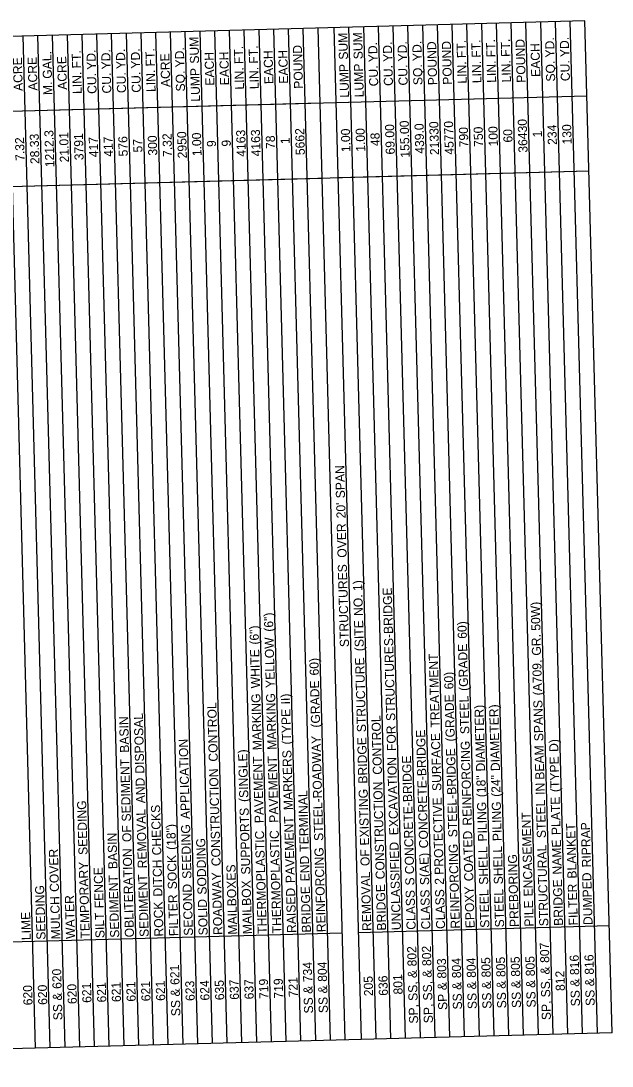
# Model space of a CAD drawing. Extents: x 1930093 to 1931323, y 596452 to 607874.
# Drawn here: x 1930614 to 1931004, y 606441 to 607132 of the extents above; entities that cross this region are included whole.
import ezdxf

# ---------------------------------------------------------------- set-up
doc = ezdxf.new("R2010")
doc.units = 0
doc.layers.add('Default', color=7, linetype='Continuous')

msp = doc.modelspace()

# ---------------------------------------------------------------- linework, layer by layer
at = {"layer": 'Default'}
for p, q in [((1930986.43, 607132.14), (1930166.75, 607110.14)), ((1930984.9, 606462.52), (1930966.94, 607131.62)), ((1930994.65, 606462.78), (1930976.69, 607131.88)), ((1931004.39, 606463.04), (1930986.43, 607132.14)), ((1930720.77, 606455.43), (1930702.81, 607124.53)), ((1930730.52, 606455.69), (1930712.56, 607124.79)), ((1930740.26, 606455.95), (1930722.3, 607125.05)), ((1930750.01, 606456.22), (1930732.05, 607125.31)), ((1930759.76, 606456.48), (1930741.79, 607125.57)), ((1930769.5, 606456.74), (1930751.54, 607125.83)), ((1930779.25, 606457), (1930761.29, 607126.1)), ((1930789, 606457.26), (1930771.03, 607126.36)), ((1930798.74, 606457.52), (1930780.78, 607126.62)), ((1930808.49, 606457.79), (1930790.53, 607126.88)), ((1930818.24, 606458.05), (1930800.27, 607127.14)), ((1930827.98, 606458.31), (1930810.02, 607127.4)), ((1930811.35, 607077.7), (1930810.02, 607127.4)), ((1930838.7, 606458.6), (1930820.74, 607127.69)), ((1930848.45, 606458.86), (1930830.49, 607127.95)), ((1930858.2, 606459.12), (1930840.23, 607128.22)), ((1930867.94, 606459.38), (1930849.98, 607128.48)), ((1930877.69, 606459.64), (1930859.73, 607128.74)), ((1930887.44, 606459.9), (1930869.47, 607129)), ((1930897.18, 606460.17), (1930879.22, 607129.26)), ((1930906.93, 606460.43), (1930888.97, 607129.52)), ((1930916.67, 606460.69), (1930898.71, 607129.79)), ((1930926.42, 606460.95), (1930908.46, 607130.05)), ((1930936.17, 606461.21), (1930918.21, 607130.31)), ((1930945.91, 606461.47), (1930927.95, 607130.57)), ((1930955.66, 606461.74), (1930937.7, 607130.83)), ((1930965.41, 606462), (1930947.45, 607131.09)), ((1930975.15, 606462.26), (1930957.19, 607131.36)), ((1930623.31, 606452.81), (1930605.34, 607121.91)), ((1930633.05, 606453.08), (1930615.09, 607122.17)), ((1930642.8, 606453.34), (1930624.84, 607122.43)), ((1930652.54, 606453.6), (1930634.58, 607122.7)), ((1930662.29, 606453.86), (1930644.33, 607122.96)), ((1930672.04, 606454.12), (1930654.08, 607123.22)), ((1930681.78, 606454.38), (1930663.82, 607123.48)), ((1930691.53, 606454.65), (1930673.57, 607123.74)), ((1930701.28, 606454.91), (1930683.32, 607124)), ((1930711.02, 606455.17), (1930693.06, 607124.27)), ((1930987.77, 607082.43), (1930168.09, 607060.43)), ((1930811.35, 607077.7), (1930168.09, 607060.43)), ((1930987.77, 607082.43), (1930822.08, 607077.99)), ((1930989.1, 607032.73), (1930169.42, 607010.72)), ((1930812.69, 607027.99), (1930198.66, 607011.51)), ((1930989.1, 607032.73), (1930823.41, 607028.28)), ((1931002.5, 606533.71), (1930836.81, 606529.26)), ((1931002.5, 606533.71), (1930836.81, 606529.26)), ((1930826.08, 606528.97), (1930182.82, 606511.7)), ((1930826.08, 606528.97), (1930212.06, 606512.49)), ((1931004.39, 606463.04), (1930184.71, 606441.04)), ((1931004.39, 606463.04), (1930184.71, 606441.04))]:
    msp.add_line(p, q, dxfattribs=at)

# ---------------------------------------------------------------- texts
for s, p in [(' SUM', (1930731.48, 607101.72)), (' SUM', (1930829.92, 607104.37)), (' SUM', (1930839.67, 607104.63)), (' YD.', (1930859.22, 607102.92)), (' YD.', (1930868.97, 607103.18)), (' YD.', (1930878.71, 607103.45)), ('POUND', (1930888.83, 607089.73)), ('POUND', (1930898.58, 607089.99)), (' FT.', (1930907.92, 607105.4)), (' FT.', (1930917.67, 607105.66)), (' FT.', (1930927.41, 607105.92)), (' FT.', (1930937.16, 607106.18)), ('POUND', (1930947.31, 607091.3)), (' YD.', (1930966.43, 607105.8)), (' YD.', (1930976.18, 607106.06)), (' GAL.', (1930634.21, 607091.75)), (' FT.', (1930653.54, 607098.57)), (' YD.', (1930663.32, 607097.66)), (' YD.', (1930673.06, 607097.92)), (' YD.', (1930682.81, 607098.19)), (' YD.', (1930692.56, 607098.45)), (' FT.', (1930702.27, 607099.88)), (' YD.', (1930721.79, 607099.23)), ('EACH', (1930741.57, 607089.38)), ('EACH', (1930751.31, 607089.64)), (' FT.', (1930760.75, 607101.45)), (' FT.', (1930770.5, 607101.71)), ('EACH', (1930780.55, 607090.43)), ('EACH', (1930790.3, 607090.69)), ('POUND', (1930800.14, 607087.35)), (' YD.', (1930849.47, 607102.66)), ('EACH', (1930956.96, 607095.16)), ('ACRE', (1930614.86, 607085.87)), ('ACRE', (1930624.61, 607086.13)), ('ACRE', (1930644.1, 607086.65)), ('ACRE', (1930712.33, 607088.48)), ('LIN.', (1930908.31, 607090.76)), ('LIN.', (1930918.06, 607091.03)), ('LIN.', (1930927.81, 607091.29)), ('LIN.', (1930937.55, 607091.55)), ('SQ.', (1930966.8, 607092.1)), ('CU.', (1930976.55, 607092.36)), ('LIN.', (1930653.93, 607083.93)), ('CU.', (1930663.68, 607083.96)), ('CU.', (1930673.43, 607084.22)), ('CU.', (1930683.18, 607084.48)), ('CU.', (1930692.92, 607084.75)), ('LIN.', (1930702.66, 607085.24)), ('SQ.', (1930722.16, 607085.53)), ('LUMP', (1930732.1, 607078.81)), ('LIN.', (1930761.14, 607086.81)), ('LIN.', (1930770.89, 607087.07)), ('LUMP', (1930830.54, 607081.45)), ('LUMP', (1930840.28, 607081.71)), ('CU.', (1930849.84, 607088.96)), ('CU.', (1930859.59, 607089.22)), ('CU.', (1930869.33, 607089.48)), ('SQ.', (1930879.08, 607089.74)), ('M.', (1930634.44, 607083.18)), ('69.00', (1930860.81, 607043.87)), ('155.00', (1930870.61, 607041.8)), ('439.0', (1930880.3, 607044.39)), ('21330', (1930890.08, 607043.49)), ('45770', (1930899.82, 607043.75)), ('36430', (1930948.55, 607045.06)), ('234', (1930967.92, 607050.24)), ('130', (1930977.67, 607050.5)), ('28.33', (1930625.92, 607037.55)), ('1212.3', (1930635.72, 607035.48)), ('21.01', (1930645.39, 607038.65)), ('3791', (1930655.11, 607040.08)), ('576', (1930684.3, 607042.61)), ('300', (1930703.79, 607043.15)), ('7.32', (1930713.57, 607042.27)), ('2950', (1930723.35, 607041.34)), ('1.00', (1930733.06, 607042.77)), ('4163', (1930762.33, 607042.38)), ('4163', (1930772.08, 607042.64)), ('78', (1930781.7, 607047.55)), ('5662', (1930801.32, 607043.46)), ('1.00', (1930831.5, 607045.41)), ('1.00', (1930841.25, 607045.67)), ('48', (1930850.9, 607049.41)), ('790', (1930909.44, 607048.67)), ('750', (1930919.19, 607048.93)), ('100', (1930928.94, 607049.19)), ('60', (1930938.62, 607051.78)), ('1', (1930958.04, 607055.2)), ('7.32', (1930616.11, 607039.65)), ('417', (1930664.81, 607042.09)), ('417', (1930674.55, 607042.35)), ('57', (1930693.98, 607045.2)), ('9', (1930742.65, 607048.84)), ('9', (1930752.4, 607049.1)), ('1', (1930791.37, 607050.73)), (' SPAN', (1930827.95, 606814.35)), (" 20'", (1930828.31, 606801.08)), (' OVER', (1930829.01, 606775.04)), ('STRUCTURES', (1930830.53, 606718.18)), (' 1)', (1930839.35, 606753.02)), (' NO.', (1930839.8, 606736.52)), (' STRUCTURES-BRIDGE', (1930861.17, 606667.12)), (' 50W)', (1930957.1, 606726.76)), (' (6")', (1930780.58, 606726.12)), (' (6")', (1930771.05, 606717.58)), (' (SITE', (1930840.42, 606713.23)), (' 60)', (1930908.47, 606721.44)), (' YELLOW', (1930781.58, 606688.96)), (' GR.', (1930957.54, 606710.27)), (' (GRADE', (1930909.4, 606686.97)), (' WHITE', (1930771.83, 606688.7)), (' 60)', (1930810.62, 606697.17)), (' STRUCTURE', (1930841.86, 606659.66)), (' TREATMENT', (1930890.54, 606662.72)), (' (A709,', (1930958.25, 606684.01)), (' 60)', (1930899.62, 606688)), (' (GRADE', (1930811.54, 606662.7)), (' MARKING', (1930772.93, 606647.78)), (' MARKING', (1930782.67, 606648.05)), (' II)', (1930791.62, 606678.05)), (' (GRADE', (1930900.54, 606653.52)), (' STEEL', (1930910.17, 606658.39)), (' SPANS', (1930959.06, 606653.7)), (' CONTROL', (1930743.87, 606640.22)), (' (TYPE', (1930792.33, 606651.49)), (' DIAMETER)', (1930920.58, 606633.68)), (' DIAMETER)', (1930930.33, 606633.94)), (' BASIN', (1930685.19, 606646.08)), (' DISPOSAL', (1930695.32, 606632.24)), (' CONTROL', (1930852.37, 606631.56)), (' FOR', (1930861.7, 606647.21)), (' CONCRETE-BRIDGE', (1930882.93, 606582.93)), (' APPLICATION', (1930725.38, 606602.23)), (' STEEL-ROADWAY', (1930813.55, 606587.79)), (' BRIDGE', (1930842.77, 606625.65)), (' SURFACE', (1930891.67, 606620.79)), (' REINFORCING', (1930911.79, 606597.92)), (' D)', (1930969, 606646.63)), (' (SINGLE)', (1930764.09, 606613.54)), (' MARKERS', (1930793.5, 606608.15)), (' STEEL-BRIDGE', (1930902.24, 606590.17)), (' BEAM', (1930959.74, 606628.25)), (' SEDIMENT', (1930686.41, 606600.61)), (' PAVEMENT', (1930774.22, 606599.52)), (' PAVEMENT', (1930783.97, 606599.78)), (' EXCAVATION', (1930863.19, 606591.54)), (' CONCRETE-BRIDGE', (1930873.64, 606565.77)), (' (TYPE', (1930969.72, 606620.07)), (' CONSTRUCTION', (1930745.73, 606571.06)), (' AND', (1930695.84, 606612.66)), (' CONSTRUCTION', (1930854.22, 606562.41)), (' (18"', (1930921.04, 606616.67)), (' (24"', (1930930.79, 606616.93)), (' IN', (1930960.01, 606618.23)), (' TERMINAL', (1930803.99, 606580.65)), (' EXISTING', (1930843.87, 606584.73)), (' SEEDING', (1930657.75, 606578.49)), (' CHECKS', (1930706.52, 606578.23)), (' PROTECTIVE', (1930893.16, 606565.36)), (' PILING', (1930921.83, 606587.39)), (' PILING', (1930931.57, 606587.65)), (' STEEL', (1930960.78, 606589.65)), (' PLATE', (1930970.48, 606591.64)), (' REMOVAL', (1930697, 606569.65)), (' SUPPORTS', (1930765.38, 606565.55)), (' ENCASEMENT', (1930952.06, 606551.06)), (' OF', (1930686.78, 606587.03)), (' (18")', (1930716.18, 606581.85)), (' SEEDING', (1930726.44, 606562.71)), (' PAVEMENT', (1930794.79, 606559.89)), (' BLANKET', (1930981.01, 606562.88)), (' RIPRAP', (1930990.56, 606570.26)), (' BASIN', (1930677.5, 606569.13)), ('THERMOPLASTIC', (1930776.13, 606528.6)), ('THERMOPLASTIC', (1930785.87, 606528.87)), (' COATED', (1930912.78, 606561.11)), (' SODDING', (1930736.48, 606552.26)), ('UNCLASSIFIED', (1930864.82, 606530.99)), ('REINFORCING', (1930903.81, 606532.03)), (' SHELL', (1930922.59, 606558.81)), (' SHELL', (1930932.34, 606559.07)), ('STRUCTURAL', (1930962.28, 606533.6)), (' NAME', (1930971.18, 606565.55)), (' COVER', (1930638.89, 606554.06)), ('OBLITERATION', (1930688.41, 606526.25)), (' SOCK', (1930716.88, 606555.79)), (' END', (1930804.52, 606561.07)), ('REINFORCING', (1930815.11, 606529.65)), (' OF', (1930844.23, 606571.15)), (' S(AE)', (1930883.59, 606558.55)), ('PREBORING', (1930942.79, 606533.08)), ('TEMPORARY', (1930659.17, 606525.46)), (' FENCE', (1930668.44, 606543.25)), (' DITCH', (1930707.25, 606550.97)), ('MAILBOXES', (1930756.63, 606528.08)), ('SEDIMENT', (1930678.66, 606525.99)), ('SEDIMENT', (1930698.15, 606526.51)), ('ROADWAY', (1930746.89, 606527.82)), ('REMOVAL', (1930845.33, 606530.46)), (' S', (1930873.84, 606558.29)), (' 2', (1930893.33, 606558.82)), ('DUMPED', (1930991.52, 606534.39)), ('SEEDING', (1930629.93, 606524.68)), ('SECOND', (1930727.39, 606527.3)), ('MAILBOX', (1930766.38, 606528.34)), ('RAISED', (1930795.62, 606529.13)), ('BRIDGE', (1930805.37, 606529.39)), ('BRIDGE', (1930855.07, 606530.72)), ('EPOXY', (1930913.55, 606532.29)), ('STEEL', (1930933.05, 606532.82)), ('BRIDGE', (1930972.03, 606533.86)), ('FILTER', (1930981.78, 606534.13)), ('MULCH', (1930639.68, 606524.94)), ('WATER', (1930649.42, 606525.2)), ('FILTER', (1930717.65, 606527.03)), ('SOLID', (1930737.14, 606527.56)), ('CLASS', (1930874.57, 606531.25)), ('CLASS', (1930884.31, 606531.51)), ('CLASS', (1930894.06, 606531.77)), ('STEEL', (1930923.3, 606532.56)), ('ROCK', (1930707.9, 606526.77)), ('PILE', (1930952.54, 606533.34)), ('LIME', (1930620.18, 606524.42)), ('SILT', (1930668.92, 606525.73)), (' 802', (1930875.28, 606504.8)), (' 802', (1930885.02, 606505.06)), (' 807', (1930963, 606507.12)), (' 734', (1930806.31, 606494.37)), (' 804', (1930816.05, 606494.63)), (' 803', (1930895, 606496.77)), (' 804', (1930904.75, 606497.01)), (' 804', (1930914.49, 606497.27)), (' 805', (1930924.24, 606497.5)), (' 805', (1930933.99, 606497.76)), (' 805', (1930943.73, 606498.02)), (' 805', (1930953.48, 606498.28)), (' 816', (1930982.72, 606499.09)), (' 816', (1930992.46, 606499.35)), (' 620', (1930640.62, 606489.92)), (' 621', (1930718.57, 606492.58)), (' &', (1930875.48, 606497.08)), (' &', (1930885.23, 606497.34)), (' &', (1930963.2, 606499.4)), ('812', (1930973.19, 606490.79)), ('621', (1930660.31, 606482.94)), ('621', (1930670.06, 606483.2)), ('621', (1930679.8, 606483.47)), ('621', (1930689.55, 606483.73)), ('621', (1930699.3, 606483.99)), ('621', (1930709.04, 606484.25)), ('623', (1930728.55, 606484.19)), ('624', (1930738.3, 606484.47)), ('635', (1930748.04, 606484.69)), ('637', (1930757.79, 606484.98)), ('637', (1930767.54, 606485.24)), ('719', (1930777.28, 606485.5)), ('719', (1930787.03, 606485.76)), ('721', (1930796.76, 606486.6)), ('205', (1930846.48, 606487.34)), ('636', (1930856.23, 606487.62)), ('801', (1930865.96, 606488.46)), (' SS,', (1930875.89, 606481.99)), (' SS,', (1930885.63, 606482.25)), (' &', (1930895.21, 606489.05)), (' &', (1930904.95, 606489.29)), (' &', (1930914.7, 606489.55)), (' &', (1930924.45, 606489.77)), (' &', (1930934.19, 606490.04)), (' &', (1930943.94, 606490.3)), (' &', (1930953.69, 606490.56)), (' SS,', (1930963.61, 606484.31)), (' &', (1930982.93, 606491.37)), (' &', (1930992.67, 606491.63)), ('620', (1930621.34, 606481.33)), ('620', (1930631.09, 606481.59)), (' &', (1930640.82, 606482.19)), ('620', (1930650.58, 606482.11)), (' &', (1930718.78, 606484.86)), (' &', (1930806.51, 606486.64)), (' &', (1930816.26, 606486.91)), ('SS', (1930905.24, 606478.54)), ('SS', (1930914.99, 606478.81)), ('SS', (1930924.74, 606479.03)), ('SS', (1930934.48, 606479.29)), ('SS', (1930944.23, 606479.55)), ('SS', (1930953.97, 606479.82)), ('SS', (1930983.21, 606480.62)), ('SS', (1930992.96, 606480.89)), ('SS', (1930641.11, 606471.45)), ('SS', (1930719.07, 606474.11)), ('SS', (1930806.8, 606475.9)), ('SS', (1930816.55, 606476.16)), ('SP', (1930895.5, 606478.23)), ('SP,', (1930963.95, 606471.54)), ('SP,', (1930876.23, 606469.22)), ('SP,', (1930885.98, 606469.48))]:
    msp.add_text(s, height=6, rotation=91.53769, dxfattribs=at).set_placement(p)

doc.saveas('drawing.dxf')
